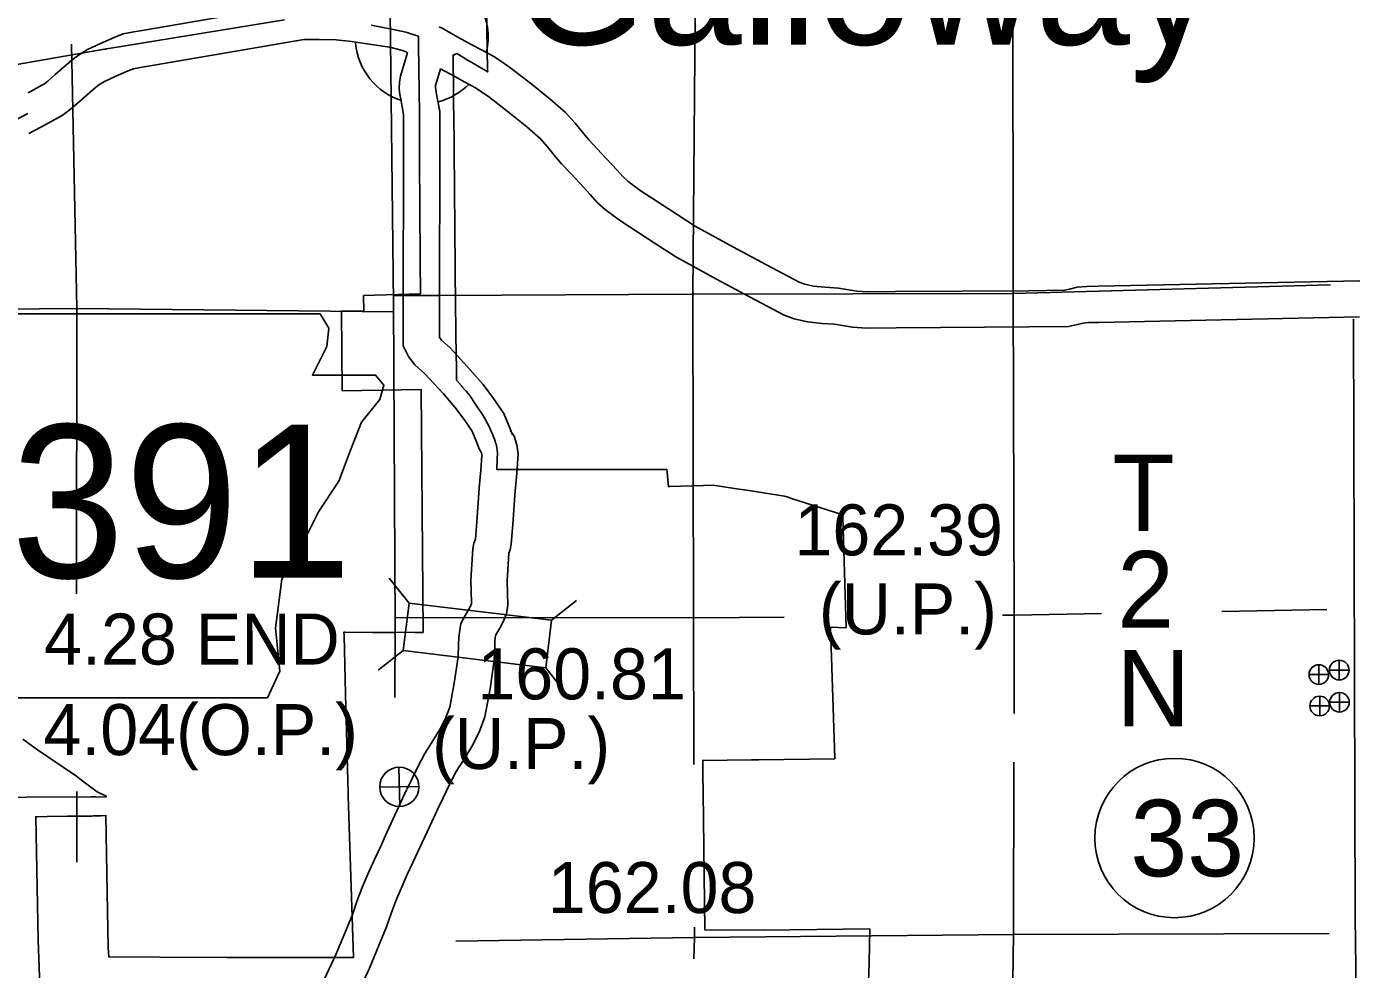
# Model space of a CAD drawing. Extents: x 1127717 to 1741049, y 2026793 to 2244711.
# Drawn here: x 1242222 to 1247728, y 2133375 to 2137280 of the extents above; entities that cross this region are included whole.
import ezdxf

# ---------------------------------------------------------------- set-up
doc = ezdxf.new("R2010")
doc.units = 0
for name, color, linetype in [('10', 7, 'Continuous'), ('15', 7, 'Continuous'), ('2', 7, 'Continuous'), ('20', 7, 'Continuous'), ('21', 7, 'Continuous'), ('24', 7, 'Continuous'), ('25', 7, 'Continuous'), ('26', 7, 'Continuous'), ('27', 7, 'Continuous'), ('30', 7, 'Continuous'), ('4', 7, 'Continuous'), ('5', 7, 'Continuous'), ('58', 7, 'Continuous'), ('6', 7, 'Continuous')]:
    doc.layers.add(name, color=color, linetype=linetype)

msp = doc.modelspace()

# ---------------------------------------------------------------- linework, layer by layer
at = {"layer": '10'}
for points in [[(1243799.9, 2137173.2), (1243794.3, 2137152.9), (1243770.9, 2137074.7), (1243766.7, 2137050), (1243766.2, 2137021.9), (1243768.5, 2136998.8), (1243772.1, 2136979.4), (1243783.7, 2136915.3)], [(1243936.6, 2137105.4), (1243917.3, 2137040.6), (1243916.5, 2137035.9), (1243916.3, 2137027.9), (1243917.1, 2137020), (1243919.6, 2137006.5), (1243933.7, 2136928.7)], [(1243933.7, 2136928.7), (1243932.5, 2135992)], [(1243783.7, 2136915.3), (1243782.5, 2135957.4)], [(1243932.5, 2135992), (1243932.4, 2135992.3), (1243940.7, 2135981.2), (1243977.1, 2135949.5), (1244060.5, 2135858.8), (1244114.3, 2135797.2), (1244156.6, 2135739.2), (1244200, 2135677.1), (1244226.1, 2135614.4), (1244235.4, 2135589.3)], [(1243782.5, 2135957.4), (1243804, 2135913.5), (1243830.3, 2135878.5), (1243872.2, 2135841.9), (1243948.8, 2135758.7), (1243997, 2135703.5), (1244034.5, 2135652), (1244067.8, 2135604.5), (1244086.5, 2135559.5), (1244098.2, 2135528)], [(1244246.4, 2135356.2), (1244253.3, 2135430.6), (1244259.2, 2135510.7), (1244252.8, 2135548.2), (1244242, 2135584), (1244226.6, 2135606.1)], [(1244097, 2135370.1), (1244103.8, 2135443.1), (1244108.3, 2135503.5), (1244106.5, 2135513.8), (1244105.3, 2135517.8), (1244098.2, 2135528)], [(1244096.9, 2135368.2), (1244087.4, 2135228.9), (1244081.5, 2135157.3), (1244081.3, 2135156.2), (1244074.9, 2135140.9), (1244070.7, 2135116.2), (1244063.1, 2134986.6), (1244065.9, 2134894.4), (1244064.8, 2134888.7), (1244062.3, 2134882.4), (1244054.5, 2134866.7), (1244039.6, 2134840.7), (1244021.8, 2134808), (1244016.7, 2134780.2), (1244013, 2134749.3), (1244011.8, 2134720.8)], [(1244246.5, 2135358), (1244237, 2135217.6), (1244230.3, 2135136.2), (1244225.4, 2135112), (1244219.9, 2135098.9), (1244213.2, 2134984.4), (1244216.3, 2134883.1), (1244209.8, 2134847.4), (1244199.4, 2134821.1), (1244186.8, 2134795.8), (1244170.6, 2134767.6), (1244165, 2134757.3), (1244162.6, 2134737.2), (1244161.6, 2134714.4)], [(1244011.8, 2134720.8), (1244009.6, 2134669.8), (1243994.1, 2134560.9), (1243975.7, 2134461.3), (1243959.4, 2134417.6), (1243935.6, 2134371.4), (1243904.6, 2134321.3), (1243872, 2134269.3), (1243841.4, 2134211.4), (1243797.1, 2134119.5)], [(1244161.6, 2134714.4), (1244159.2, 2134656), (1244142.2, 2134536.7), (1244120.8, 2134421.2), (1244096.8, 2134356.8), (1244066.2, 2134297.5), (1244031.9, 2134242), (1244002, 2134194.3), (1243975.3, 2134143.7), (1243932.2, 2134054.3)], [(1243796.5, 2134118.3), (1243764.8, 2134049.6), (1243714.8, 2133942.5), (1243687.8, 2133882.9), (1243663.1, 2133830.1), (1243636.1, 2133769.8), (1243611.9, 2133713.8), (1243590.8, 2133656.1), (1243573.1, 2133605.1), (1243504.7, 2133439.6), (1243456.7, 2133335.2), (1243439.3, 2133301.6), (1243428.4, 2133270.6), (1243412, 2133204.1), (1243332.4, 2132858.6)], [(1243932.7, 2134055.5), (1243900.9, 2133986.5), (1243851.1, 2133879.9), (1243824.1, 2133820.1), (1243799.5, 2133767.6), (1243773.4, 2133709.4), (1243751.3, 2133658.2), (1243732.1, 2133605.8), (1243713.4, 2133551.8), (1243642.2, 2133379.6), (1243591.5, 2133269.3), (1243577.4, 2133242.1), (1243572.4, 2133227.7), (1243557.9, 2133169.2), (1243485.6, 2132855.4)]]:
    msp.add_lwpolyline(points, dxfattribs=at)
at = {"layer": '15'}
for points in [[(1242228.1, 2137005.3), (1242288.1, 2137037.9), (1242295.6, 2137043.4), (1242309.9, 2137054.3), (1242340.9, 2137080.9), (1242411, 2137142.8), (1242436.4, 2137161.8), (1242474, 2137185.2), (1242527.7, 2137209.9), (1242585.3, 2137234.9), (1242622.7, 2137249.3), (1242665.9, 2137258.2), (1242709.8, 2137265.5), (1243312.7, 2137368.1), (1243354.8, 2137376), (1243395.8, 2137376.8), (1243435.9, 2137376.7), (1243515.2, 2137374.8), (1243587.7, 2137366.3), (1243682.5, 2137353), (1243757.1, 2137342.3), (1243777.3, 2137336.7)], [(1243931.1, 2137279.2), (1243941, 2137274.1), (1244012.1, 2137235), (1244067.2, 2137204.6), (1244109.6, 2137182), (1244160.2, 2137153.9)], [(1242231.6, 2136837.4), (1242280.5, 2136863.1), (1242368.8, 2136911), (1242385.7, 2136923.4), (1242404.4, 2136937.8), (1242439.3, 2136967.8), (1242505.7, 2137026.3), (1242521.2, 2137037.9), (1242545.2, 2137052.9), (1242588.8, 2137072.9), (1242642.3, 2137096.1), (1242665.1, 2137104.9), (1242693.2, 2137110.7), (1242734.7, 2137117.5), (1243339, 2137220.4), (1243370.3, 2137226.3), (1243397.2, 2137226.8), (1243433.9, 2137226.7), (1243504.6, 2137225), (1243568.5, 2137217.5), (1243661.4, 2137204.5), (1243726.4, 2137195.2), (1243779.2, 2137180.6), (1243797.5, 2137174.3)], [(1244160.2, 2137153.9), (1244222.9, 2137112.1), (1244311.3, 2137043.5), (1244391.2, 2136979.4), (1244454.7, 2136924.1), (1244494.6, 2136879.8), (1244524.8, 2136842.6), (1244551.1, 2136810.5), (1244585.9, 2136773.4), (1244623.6, 2136733.3), (1244668.3, 2136685.2), (1244692, 2136658.3), (1244714.9, 2136638.2), (1244764.2, 2136601.4), (1244880.9, 2136525.5), (1244988.9, 2136454.4), (1245151.1, 2136366.3), (1245288.3, 2136293.5), (1245423.3, 2136221.6), (1245446.2, 2136212.7), (1245481.4, 2136204.8), (1245530, 2136200), (1245586.5, 2136196.4), (1245661.2, 2136184.1), (1245706.4, 2136180.7), (1245822.5, 2136182.7), (1246373.5, 2136185.9), (1246521.7, 2136187.5), (1246542.4, 2136192), (1246574.6, 2136200), (1246614.2, 2136203.7), (1246661.3, 2136204.1), (1247745.5, 2136227)], [(1243936.6, 2137105.4), (1243995.7, 2137072.8), (1244037.8, 2137050.3), (1244084.6, 2137024.3)], [(1244079.5, 2137027.4), (1244135.2, 2136990.2), (1244218.4, 2136925.7), (1244295, 2136864.3), (1244349.3, 2136816.9), (1244380.6, 2136782.2), (1244408.5, 2136747.9), (1244438.2, 2136711.6), (1244476.6, 2136670.7), (1244514, 2136630.9), (1244557.1, 2136584.5), (1244586, 2136551.8), (1244620.5, 2136521.5), (1244678.4, 2136478.3), (1244798.8, 2136400), (1244911.7, 2136325.6), (1245080.2, 2136234.2), (1245217.8, 2136161), (1245360.7, 2136085), (1245402.4, 2136068.8), (1245457.6, 2136056.4), (1245518, 2136050.4), (1245569.5, 2136047.2), (1245643.3, 2136035), (1245702.1, 2136030.6), (1245824.3, 2136032.7), (1246374.7, 2136035.9), (1246538.7, 2136037.7), (1246576.5, 2136045.9), (1246599.8, 2136051.7), (1246621.9, 2136053.8), (1246663.5, 2136054.1), (1247745, 2136077)], [(1242020.6, 2136811.2), (1242227.5, 2136920)]]:
    msp.add_lwpolyline(points, dxfattribs=at)
at = {"layer": '2'}
msp.add_lwpolyline([(1247719.9, 2136068.2), (1247726, 2133591.9), (1247745.1, 2132243.6)], dxfattribs=at)
at = {"layer": '20'}
for p, q in [((1243806.5, 2134891.8), (1243724.9, 2134995.6)), ((1244396.2, 2134821), (1244500, 2134902.6)), ((1243782.9, 2134695.2), (1243679.1, 2134613.6)), ((1244372.7, 2134624.4), (1244454.2, 2134520.6))]:
    msp.add_line(p, q, dxfattribs=at)
msp.add_lwpolyline([(1243782.9, 2134695.2), (1244372.7, 2134624.4), (1244396.2, 2134821), (1243806.5, 2134891.8)], close=True, dxfattribs=at)
at = {"layer": '21'}
msp.add_lwpolyline([(1241917.3, 2136090.2), (1241993.5, 2135582.7), (1241959.6, 2134812.9), (1242027.3, 2134770.6), (1242154.2, 2134770.6), (1242154.2, 2134500), (1243220, 2134500), (1243270.8, 2134609.9), (1243253.9, 2134787.6), (1243279.2, 2134990.6), (1243372.3, 2135151.3), (1243431.5, 2135269.7), (1243516.1, 2135396.6), (1243566.8, 2135532), (1243609.1, 2135641.9), (1243685.3, 2135735), (1243702.2, 2135794.2), (1243668.3, 2135836.5), (1243406.1, 2135836.5), (1243465.3, 2135954.9), (1243473.8, 2136031), (1243438.7, 2136089.5)], close=True, dxfattribs=at)
at = {"layer": '24'}
for start, end in [(346.4695, 74.2639), (185.0338, 252.1304), (284.5564, 315.4275)]:
    msp.add_arc((1243859.3, 2137235), 275, start, end, dxfattribs=at)
at = {"layer": '26'}
for p, q in [((1247576.1, 2134555.3), (1247576.1, 2134636.6)), ((1247619.8, 2134614.6), (1247701.1, 2134614.6)), ((1247660.5, 2134574), (1247660.5, 2134655.2)), ((1247535.5, 2134596), (1247616.7, 2134596)), ((1247579.5, 2134425.2), (1247579.5, 2134506.5)), ((1247661.6, 2134440.6), (1247661.6, 2134521.8)), ((1247538.9, 2134465.9), (1247620.1, 2134465.9)), ((1247621, 2134481.2), (1247702.3, 2134481.2)), ((1243768.2, 2134049.9), (1243764.5, 2134212.6)), ((1243685, 2134129.4), (1243847.7, 2134133.1))]:
    msp.add_line(p, q, dxfattribs=at)
for centre, radius in [((1247576.1, 2134596), 40.6), ((1247660.5, 2134614.6), 40.6), ((1247579.5, 2134465.9), 40.6), ((1247661.6, 2134481.2), 40.6), ((1243766.3, 2134131.2), 81.4)]:
    msp.add_circle(centre, radius, dxfattribs=at)
at = {"layer": '27'}
msp.add_circle((1246978.1, 2133919), 330, dxfattribs=at)
at = {"layer": '4'}
msp.add_lwpolyline([(1243747.4, 2134501.7), (1243748.7, 2134801.1), (1243742.4, 2136135.9), (1243727.4, 2137462.4), (1243722.8, 2138403.9)], dxfattribs=at)
at = {"layer": '5'}
for points in [[(1245008.2, 2138758.5), (1244993.1, 2137486.7), (1244981.8, 2136170.8), (1244985.7, 2134830.4), (1244987.2, 2134223.4)], [(1246313.2, 2134435.1), (1246314.3, 2134845.1), (1246309.2, 2136177.5), (1246308.4, 2137514), (1246311.7, 2138782.2)], [(1242429.3, 2134929.9), (1242429.9, 2136113.8), (1242407.7, 2137206.9)], [(1243928.1, 2136165.8), (1244980.3, 2136171.3), (1246311.3, 2136174), (1247623.8, 2136209.8)], [(1243742.4, 2136165.5), (1243928.1, 2136165.8)], [(1242116.8, 2136109.8), (1242431.9, 2136112.4), (1243742.8, 2136098.3)], [(1243960.4, 2134831.9), (1243748.6, 2134831.7)], [(1243960.4, 2134831.9), (1244988.1, 2134831), (1245360.5, 2134834.1)], [(1246264.8, 2134841.7), (1246314.9, 2134842.1), (1246674.9, 2134848.5)], [(1247173.9, 2134857.5), (1247609.4, 2134865.3)], [(1243748.3, 2134770), (1243656.4, 2134770.6)], [(1246292.8, 2132227), (1246310.7, 2133522), (1246312.6, 2134233)], [(1242430.3, 2133819.3), (1242430, 2134111.2)], [(1244000.8, 2133492.3), (1244988.6, 2133507), (1246310.8, 2133519), (1247618.8, 2133523)], [(1244989, 2133549.9), (1244989.1, 2133505), (1244986.7, 2133418.3)]]:
    msp.add_lwpolyline(points, dxfattribs=at)
at = {"layer": '6'}
for points in [[(1244126.3, 2137443.3), (1244132.2, 2137101.1), (1244132.2, 2137099.6), (1244132.3, 2137097.9), (1244132.4, 2137091.9), (1244047.8, 2137142.7), (1244004, 2137168), (1243999.6, 2137166.1), (1243996.5, 2137164.8), (1243993.3, 2137163.3), (1243990.6, 2137162.2), (1243989.2, 2137161.6), (1243990.7, 2137009.4), (1243991.4, 2136933.7), (1243991.5, 2136932.1), (1243991.5, 2136930.4), (1243999.4, 2136119.7), (1244000.5, 2136034.4), (1244000.6, 2136032.9), (1244000.6, 2136031.4), (1244000.9, 2136006.6), (1244000.9, 2136004.7), (1244001, 2136003), (1244001.9, 2135929.8), (1244002.9, 2135857.6), (1244003, 2135849.9), (1244003.4, 2135818.1), (1244003.5, 2135815.8), (1244023.9, 2135791.8), (1244026, 2135789.3), (1244040.9, 2135771.9), (1244042.7, 2135769.9), (1244050.9, 2135760.5), (1244057.9, 2135751.8), (1244060.2, 2135748.9), (1244066.6, 2135739.4), (1244072.9, 2135730.3), (1244094.8, 2135697.3), (1244101.6, 2135686.9), (1244108.1, 2135677), (1244122.8, 2135652.3), (1244126.4, 2135645.7), (1244137.2, 2135625.7), (1244142, 2135616), (1244150.6, 2135594.5), (1244153.2, 2135589), (1244158.3, 2135575.9), (1244158.6, 2135575.1), (1244163, 2135563.3), (1244166.8, 2135552), (1244166.9, 2135551.4), (1244170.4, 2135536.5), (1244172.4, 2135513.8), (1244172.2, 2135487.6), (1244170, 2135445.4), (1244174.8, 2135445.4), (1244176.9, 2135445.4), (1244179, 2135445.4), (1244874.6, 2135445.8), (1244875.8, 2135434.1), (1244882.1, 2135374.2), (1244886.3, 2135374.3), (1245073.3, 2135379.9), (1245074.4, 2135379.7), (1245174.4, 2135364.3), (1245194.5, 2135361.2), (1245195.6, 2135361), (1245196.8, 2135360.8), (1245361.7, 2135335.3), (1245373.3, 2135331.6), (1245383.7, 2135328.2), (1245391.7, 2135325.6), (1245603.2, 2135257.4), (1245603.5, 2135247.3), (1245617.2, 2134789.6), (1245553.3, 2134793), (1245570.4, 2134250), (1245570.5, 2134247.6), (1245255, 2134243.4), (1245247.1, 2134243.2), (1245244.2, 2134243.2), (1245244.1, 2134243.2), (1245241.5, 2134243.2), (1245238.8, 2134243.1), (1245235.2, 2134243.1), (1245232.7, 2134243)], [(1242286.2, 2133042.6), (1242269.8, 2133496.4), (1242260.1, 2134007.3), (1242307.6, 2134007.9), (1242390.9, 2134009), (1242458.6, 2134009.8), (1242492.5, 2134010.2), (1242498.4, 2134010.3), (1242506.3, 2134010.4), (1242531.6, 2134010.7), (1242550.8, 2134011.9), (1242556.3, 2133693), (1242560.2, 2133465), (1242562.1, 2133427.2), (1242774.1, 2133426.1), (1243049.6, 2133424.7), (1243082.7, 2133424.5), (1243166.1, 2133424.1), (1243182.3, 2133424.2), (1243520.2, 2133424.4), (1243576.2, 2133424.4), (1243554.1, 2134093.8), (1243554.1, 2134095.7), (1243553.9, 2134100.9), (1243553.9, 2134101.5), (1243553.8, 2134102.7), (1243553.8, 2134105.5), (1243543.5, 2134515), (1243537.3, 2134759.5), (1243537, 2134772.3), (1243539, 2134772.3), (1243541.3, 2134772.3), (1243830.5, 2134770.8), (1243852.4, 2134770.7), (1243864.7, 2134770.6), (1243857, 2135776.6), (1243529.7, 2135771.5), (1243526.1, 2136101.8), (1243619.6, 2136103.2), (1243617.7, 2136165.9), (1243854, 2136172.8), (1243852.9, 2136309.2), (1243851.2, 2136537.4), (1243851.2, 2136539.4), (1243851.2, 2136541.7), (1243849.8, 2136715.9), (1243849.5, 2136945.1), (1243849.5, 2136956.3), (1243849.4, 2136959.3), (1243849.2, 2136974.4), (1243848.9, 2136991.8), (1243848.9, 2136993.1), (1243848.9, 2136994.5), (1243848.7, 2137005.1), (1243848, 2137054.7), (1243847.8, 2137064.3), (1243847.7, 2137072.6), (1243845.1, 2137238), (1243845.1, 2137239.6), (1243813.5, 2137250.1), (1243799.1, 2137254.9), (1243793.2, 2137256.9), (1243773.3, 2137261), (1243721.9, 2137271.7), (1243706.2, 2137274.9), (1243649.9, 2137285.1)], [(1243290.5, 2137307.9), (1242563.2, 2137189.1)], [(1242563.2, 2137189.1), (1242553.4, 2137187.4), (1242548.9, 2137186.6), (1242544.6, 2137185.9), (1241880.4, 2137070.3), (1241874.6, 2137069.3), (1241874.8, 2137036.7)], [(1242206.1, 2134328.5), (1242266.7, 2134283.9), (1242428.3, 2134175.1), (1242449.6, 2134158.8), (1242487.8, 2134129.9), (1242514.3, 2134109.7), (1242551.2, 2134093), (1242551.2, 2134092.7), (1242551.2, 2134088.9), (1242507.9, 2134089.3), (1242490, 2134089.2), (1241951.4, 2134086.4)], [(1245232.7, 2134243), (1245229.9, 2134243), (1245227.5, 2134243), (1245226.7, 2134243), (1245224.8, 2134242.9), (1245023.3, 2134240.2), (1245023.4, 2134235.7), (1245023.4, 2134233.5), (1245023.6, 2134218.2), (1245024.2, 2134173.5), (1245025, 2134117.9), (1245025, 2134114.7), (1245025.1, 2134108.5), (1245032.7, 2133538.6), (1245275, 2133537.6), (1245715.7, 2133542.5), (1245712.4, 2133402.4), (1245712.4, 2133400.7), (1245712.3, 2133398.7), (1245710.6, 2133323.5)]]:
    msp.add_lwpolyline(points, dxfattribs=at)

# ---------------------------------------------------------------- texts
at = {"layer": '21'}
msp.add_text('391', height=633.6, dxfattribs=at).set_placement((1242157.1, 2134997.2))
at = {"layer": '24'}
msp.add_text('Galloway', height=528, dxfattribs=at).set_placement((1244242.7, 2137205.4))
at = {"layer": '25'}
msp.add_text('4.28 END', height=211.2, dxfattribs=at).set_placement((1242294.9, 2134637.6))
at = {"layer": '27'}
msp.add_text('33', height=316.8, dxfattribs=at).set_placement((1246795.1, 2133760.6))
at = {"layer": '30'}
for s, p in [('T', (1246720.4, 2135190.1)), ('2', (1246740.6, 2134790.9)), ('N', (1246737.3, 2134381.4))]:
    msp.add_text(s, height=316.8, dxfattribs=at).set_placement(p)
at = {"layer": '58'}
for s, p in [('162.39', (1245403.3, 2135089.7)), ('(U.P.)', (1245504.7, 2134762.2)), ('160.81', (1244089.6, 2134493.3)), ('4.04(O.P.)', (1242291.9, 2134262.3)), ('(U.P.)', (1243902.4, 2134204.8)), ('162.08', (1244381.9, 2133608.3))]:
    msp.add_text(s, height=211.2, dxfattribs=at).set_placement(p)

doc.saveas('drawing.dxf')
